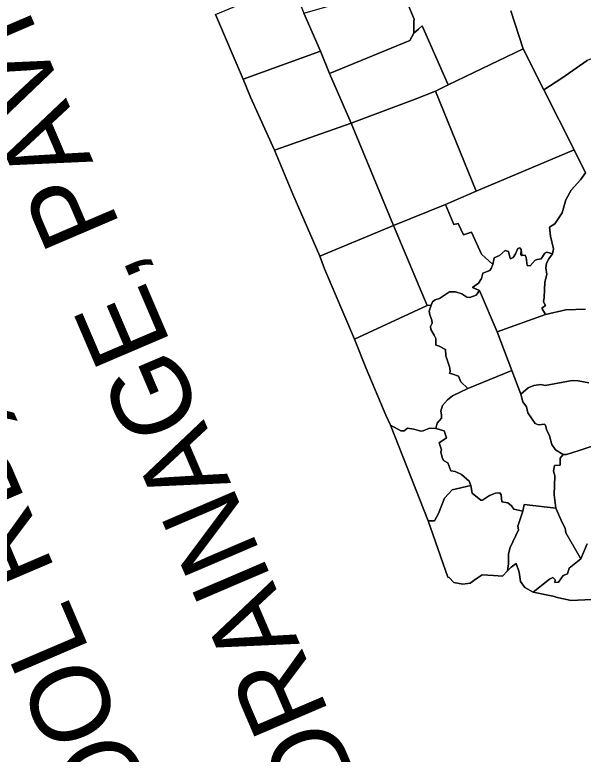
# Model space of a CAD drawing. Extents: x 1550250 to 1553210, y 808906 to 812497.
# Drawn here: x 1551099 to 1551255.1, y 810536 to 810739.3 of the extents above; entities that cross this region are included whole.
import ezdxf

# ---------------------------------------------------------------- set-up
doc = ezdxf.new("R2010")
doc.units = 0
doc.layers.add('P_RDY_Dimension_Text', color=7, linetype='Continuous')
doc.layers.add('Sheet_Data_Field_CELL', color=7, linetype='Continuous')

msp = doc.modelspace()

# ---------------------------------------------------------------- linework, layer by layer
at = {"layer": 'P_RDY_Dimension_Text'}
for points in [[(1551161.74, 810721.58), (1551154.06, 810739.31), (1551175.06, 810748.13), (1551178.36, 810739.68), (1551182.94, 810729.24), (1551161.74, 810721.58)], [(1551182.94, 810729.24), (1551178.36, 810739.68), (1551204.79, 810747.3), (1551208.64, 810738.1), (1551208.56, 810737.4), (1551208.6, 810734.25), (1551207.45, 810732.17), (1551185.41, 810723.16), (1551182.94, 810729.24)], [(1551235.21, 810740.38), (1551238.66, 810729.86), (1551218.05, 810720.05), (1551210.87, 810736.27), (1551209.84, 810735.33), (1551208.6, 810734.25), (1551208.56, 810737.4), (1551208.64, 810738.1), (1551204.79, 810747.3)], [(1551154.06, 810739.31), (1551161.74, 810721.58), (1551163.67, 810716.63), (1551170.28, 810702.09), (1551175.3, 810689.91), (1551182.8, 810672.93), (1551184.07, 810669.38), (1551192.26, 810650.09), (1551195.53, 810642.04), (1551200.89, 810629.19), (1551202.16, 810626.41), (1551212.55, 810600.12), (1551217.97, 810584.69), (1551218.26, 810584.6), (1551219.58, 810583.23), (1551222.04, 810582.69), (1551224.09, 810583), (1551225.71, 810584.23), (1551227.38, 810585.3), (1551230.5, 810585.13), (1551232.95, 810584.94), (1551234.31, 810586.44), (1551235.32, 810587.41), (1551236.67, 810588.39), (1551237.5, 810586.03), (1551237.89, 810583.45), (1551239.04, 810581.78), (1551241.36, 810580.53), (1551247.25, 810579.32), (1551247.63, 810579.17), (1551251.81, 810578.26), (1551257.36, 810578.52)], [(1551265.99, 810739.56), (1551265.11, 810736.8), (1551264.2, 810735.13), (1551263.81, 810733.42), (1551262.28, 810732.86), (1551260.72, 810731.45), (1551260.27, 810730.58), (1551260.7, 810729.58), (1551260.71, 810728.9), (1551259.95, 810728.29), (1551256.16, 810726.73), (1551249.22, 810721.82), (1551244.26, 810718.6), (1551238.66, 810729.86), (1551235.21, 810740.38)], [(1551208.6, 810734.25), (1551209.84, 810735.33), (1551210.87, 810736.27), (1551218.05, 810720.05), (1551214.56, 810718.23), (1551208.96, 810716.05), (1551191.37, 810709.47), (1551185.41, 810723.16), (1551207.45, 810732.17), (1551208.6, 810734.25)], [(1551161.74, 810721.58), (1551182.94, 810729.24), (1551185.41, 810723.16), (1551191.37, 810709.47), (1551170.28, 810702.09), (1551163.67, 810716.63), (1551161.74, 810721.58)], [(1551218.05, 810720.05), (1551238.66, 810729.86), (1551244.26, 810718.6), (1551252.6, 810702.1), (1551225.75, 810690.81), (1551214.56, 810718.23), (1551218.05, 810720.05)], [(1551252.6, 810702.1), (1551244.26, 810718.6), (1551249.22, 810721.82), (1551256.16, 810726.73)], [(1551191.37, 810709.47), (1551208.96, 810716.05), (1551214.56, 810718.23), (1551225.75, 810690.81), (1551217.26, 810687.07), (1551203.02, 810681.34), (1551191.37, 810709.47)], [(1551175.3, 810689.91), (1551170.28, 810702.09), (1551191.37, 810709.47), (1551203.02, 810681.34), (1551182.8, 810672.93), (1551175.3, 810689.91)], [(1551219.56, 810681.58), (1551217.26, 810687.07), (1551225.75, 810690.81), (1551252.6, 810702.1), (1551255.79, 810695.77), (1551254.36, 810693.86), (1551251.81, 810691.07), (1551250.34, 810688.38), (1551249.35, 810684.8), (1551247.29, 810681.78), (1551245.84, 810680.89), (1551246.17, 810678.41), (1551247, 810674.96), (1551246.69, 810673.59), (1551245.14, 810674.04), (1551244.55, 810673.71), (1551243.53, 810672.16), (1551242.48, 810671.97), (1551241.93, 810671.83), (1551240.57, 810670.27), (1551239.72, 810670.3), (1551239.46, 810672.55), (1551239.13, 810673.14), (1551238.3, 810673.1), (1551238, 810673.28), (1551238.03, 810674.74), (1551237.74, 810675.18), (1551237.19, 810675.03), (1551236.48, 810673.56), (1551235.91, 810672.56), (1551235.16, 810672.19), (1551234.95, 810672.65), (1551234.63, 810674.19), (1551233.71, 810674.46), (1551232.12, 810673.11), (1551230.69, 810672.47), (1551230.25, 810670.64), (1551227.13, 810673.43), (1551224.42, 810679.5), (1551222.25, 810678.76), (1551220.74, 810681.89), (1551219.56, 810681.58)], [(1551255.79, 810695.77), (1551252.6, 810702.1)], [(1551243.79, 810658.61), (1551244.79, 810659.31), (1551244.17, 810660.34), (1551244.37, 810661.51), (1551244.57, 810665.76), (1551245.1, 810667.87), (1551244.87, 810669.69), (1551245.02, 810671.01), (1551245.63, 810672.2), (1551246.69, 810673.59), (1551247, 810674.96), (1551246.17, 810678.41), (1551245.84, 810680.89), (1551247.29, 810681.78), (1551249.35, 810684.8), (1551250.34, 810688.38), (1551251.81, 810691.07), (1551254.36, 810693.86), (1551255.79, 810695.77)], [(1551212.26, 810659.31), (1551203.02, 810681.34), (1551217.26, 810687.07), (1551219.56, 810681.58), (1551220.74, 810681.89), (1551222.25, 810678.76), (1551224.42, 810679.5), (1551227.13, 810673.43), (1551230.25, 810670.64), (1551229.87, 810669.52), (1551229.42, 810668.97), (1551227.51, 810668.21), (1551227.14, 810666.74), (1551226.37, 810665.51), (1551224.74, 810664.31), (1551225.71, 810663.87), (1551226.67, 810663.44), (1551225.74, 810662.16), (1551223.96, 810661.52), (1551223.16, 810661.66), (1551221.81, 810662.59), (1551220.07, 810663.08), (1551218.38, 810663.06), (1551217.59, 810662.51), (1551215.65, 810661.23), (1551214.46, 810660.92), (1551213.75, 810660.39), (1551213.33, 810659.42), (1551212.26, 810659.31)], [(1551182.8, 810672.93), (1551203.02, 810681.34), (1551212.26, 810659.31), (1551192.26, 810650.09), (1551184.07, 810669.38), (1551182.8, 810672.93)], [(1551224.74, 810664.31), (1551226.37, 810665.51), (1551227.14, 810666.74), (1551227.51, 810668.21), (1551229.42, 810668.97), (1551229.87, 810669.52), (1551230.25, 810670.64), (1551230.69, 810672.47), (1551232.12, 810673.11), (1551233.71, 810674.46), (1551234.63, 810674.19), (1551234.95, 810672.65), (1551235.16, 810672.19), (1551235.91, 810672.56), (1551236.48, 810673.56), (1551237.19, 810675.03), (1551237.74, 810675.18), (1551238.03, 810674.74), (1551238, 810673.28), (1551238.3, 810673.1), (1551239.13, 810673.14), (1551239.46, 810672.55), (1551239.72, 810670.3), (1551240.57, 810670.27), (1551241.93, 810671.83), (1551242.48, 810671.97), (1551243.53, 810672.16), (1551244.55, 810673.71), (1551245.14, 810674.04), (1551246.69, 810673.59), (1551245.63, 810672.2), (1551245.02, 810671.01), (1551244.87, 810669.69), (1551245.1, 810667.87), (1551244.57, 810665.76), (1551244.37, 810661.51), (1551244.17, 810660.34), (1551244.79, 810659.31), (1551243.79, 810658.61), (1551244.76, 810656.9), (1551231.5, 810652.09), (1551226.67, 810663.44), (1551225.71, 810663.87), (1551224.74, 810664.31)], [(1551213.25, 810652.76), (1551213.19, 810653.61), (1551213.63, 810654.5), (1551213.49, 810655.33), (1551212.95, 810656.73), (1551212.82, 810657.82), (1551213.33, 810659.42), (1551213.75, 810660.39), (1551214.46, 810660.92), (1551215.65, 810661.23), (1551217.59, 810662.51), (1551218.38, 810663.06), (1551220.07, 810663.08), (1551221.81, 810662.59), (1551223.16, 810661.66), (1551223.96, 810661.52), (1551225.74, 810662.16), (1551226.67, 810663.44), (1551231.5, 810652.09), (1551235.49, 810641.46), (1551223.42, 810636.51), (1551221.46, 810638.4), (1551220.89, 810639.88), (1551219.28, 810640.49), (1551218.36, 810640.76), (1551218.53, 810641.06), (1551218.5, 810642.09), (1551218.4, 810642.49), (1551218.24, 810643.06), (1551217.41, 810645.51), (1551217.29, 810647.2), (1551215.32, 810648.23), (1551214.65, 810648.48), (1551214.6, 810649.33), (1551214.59, 810650.28), (1551214.18, 810651.2), (1551213.25, 810652.76)], [(1551212.26, 810659.31), (1551213.33, 810659.42), (1551212.82, 810657.82), (1551212.95, 810656.73), (1551213.49, 810655.33), (1551213.63, 810654.5), (1551213.19, 810653.61), (1551213.25, 810652.76), (1551214.18, 810651.2), (1551214.59, 810650.28), (1551214.6, 810649.33), (1551214.65, 810648.48), (1551215.32, 810648.23), (1551217.29, 810647.2), (1551217.41, 810645.51), (1551218.24, 810643.06), (1551218.4, 810642.49), (1551218.5, 810642.09), (1551218.53, 810641.06), (1551218.36, 810640.76), (1551219.28, 810640.49), (1551220.89, 810639.88), (1551221.46, 810638.4), (1551223.42, 810636.51), (1551219.2, 810634.52), (1551217.81, 810633.37), (1551216.43, 810631.88), (1551216.01, 810630.3), (1551216.2, 810629.31), (1551216.2, 810628.36), (1551214.96, 810626.99), (1551214.67, 810625.53), (1551212.85, 810625.65), (1551211.19, 810624.86), (1551210.54, 810624.77), (1551208.58, 810625.37), (1551206.82, 810625.58), (1551205.89, 810624.9), (1551205.03, 810624.93), (1551202.16, 810626.41), (1551200.89, 810629.19), (1551195.53, 810642.04), (1551192.26, 810650.09), (1551212.26, 810659.31)], [(1551255.77, 810658.37), (1551250.35, 810658.13), (1551244.76, 810656.9), (1551243.79, 810658.61)], [(1551244.76, 810656.9), (1551250.35, 810658.13), (1551255.77, 810658.37)], [(1551256.67, 810638.06), (1551253.71, 810638.63), (1551252.09, 810638.71), (1551244.65, 810637.39), (1551243.5, 810637.59), (1551241.54, 810637.33), (1551240, 810636.74), (1551238.02, 810635), (1551235.49, 810641.46), (1551231.5, 810652.09), (1551244.76, 810656.9)], [(1551214.67, 810625.53), (1551214.96, 810626.99), (1551216.2, 810628.36), (1551216.2, 810629.31), (1551216.01, 810630.3), (1551216.43, 810631.88), (1551217.81, 810633.37), (1551219.2, 810634.52), (1551223.42, 810636.51), (1551235.49, 810641.46), (1551238.02, 810635), (1551238.51, 810632.9), (1551239.58, 810631.47), (1551239.94, 810629.84), (1551241.95, 810626.86), (1551242.81, 810626.49), (1551244.46, 810626.68), (1551244.78, 810626.42), (1551245.01, 810625.28), (1551245.84, 810623.53), (1551246.5, 810621.12), (1551247.5, 810619.67), (1551249.64, 810618.37), (1551248.82, 810617.37), (1551248.83, 810615.48), (1551247.27, 810615.31), (1551246.91, 810613.83), (1551247.29, 810612.47), (1551247.13, 810607.26), (1551247.56, 810603.58), (1551238.92, 810604.66), (1551238.5, 810602.82), (1551236.05, 810603.35), (1551235.44, 810604.31), (1551234.38, 810605.05), (1551232.76, 810605.39), (1551232.56, 810607.32), (1551232.17, 810607.82), (1551230.99, 810607.75), (1551229.37, 810607.14), (1551227.44, 810605.83), (1551227.02, 810605.8), (1551224.61, 810607.74), (1551224.26, 810609.89), (1551223.77, 810611.06), (1551221.64, 810612.9), (1551219.96, 810613.74), (1551218.72, 810613.92), (1551217.94, 810616.13), (1551216.74, 810616.76), (1551216.36, 810617.52), (1551216.02, 810619.07), (1551216.21, 810619.64), (1551215.57, 810621.63), (1551217.52, 810622.93), (1551216.89, 810624.92), (1551214.67, 810625.53)], [(1551238.02, 810635), (1551240, 810636.74), (1551241.54, 810637.33), (1551243.5, 810637.59), (1551244.65, 810637.39), (1551252.09, 810638.71), (1551253.71, 810638.63), (1551256.67, 810638.06)], [(1551257.88, 810620.79), (1551254, 810619.47), (1551250.5, 810618.34), (1551249.64, 810618.37), (1551247.5, 810619.67), (1551246.5, 810621.12), (1551245.84, 810623.53), (1551245.01, 810625.28), (1551244.78, 810626.42), (1551244.46, 810626.68), (1551242.81, 810626.49), (1551241.95, 810626.86), (1551239.94, 810629.84), (1551239.58, 810631.47), (1551238.51, 810632.9), (1551238.02, 810635)], [(1551202.16, 810626.41), (1551205.03, 810624.93), (1551205.89, 810624.9), (1551206.82, 810625.58), (1551208.58, 810625.37), (1551210.54, 810624.77), (1551211.19, 810624.86), (1551212.85, 810625.65), (1551214.67, 810625.53), (1551216.89, 810624.92), (1551217.52, 810622.93), (1551215.57, 810621.63), (1551216.21, 810619.64), (1551216.02, 810619.07), (1551216.36, 810617.52), (1551216.74, 810616.76), (1551217.94, 810616.13), (1551218.72, 810613.92), (1551219.96, 810613.74), (1551221.64, 810612.9), (1551223.77, 810611.06), (1551224.26, 810609.89), (1551219.14, 810608.67), (1551218.1, 810607.52), (1551216.97, 810606.35), (1551215.39, 810602.19), (1551214.25, 810600.15), (1551212.55, 810600.12), (1551202.16, 810626.41)], [(1551256.17, 810593.81), (1551254.44, 810589.7), (1551250.3, 810596.84), (1551250.2, 810598.1), (1551249.34, 810599.68), (1551247.56, 810603.58), (1551247.13, 810607.26), (1551247.29, 810612.47), (1551246.91, 810613.83), (1551247.27, 810615.31), (1551248.83, 810615.48), (1551248.82, 810617.37), (1551249.64, 810618.37), (1551250.5, 810618.34), (1551254, 810619.47), (1551257.88, 810620.79)], [(1551212.55, 810600.12), (1551214.25, 810600.15), (1551215.39, 810602.19), (1551216.97, 810606.35), (1551218.1, 810607.52), (1551219.14, 810608.67), (1551224.26, 810609.89), (1551224.61, 810607.74), (1551227.02, 810605.8), (1551227.44, 810605.83), (1551229.37, 810607.14), (1551230.99, 810607.75), (1551232.17, 810607.82), (1551232.56, 810607.32), (1551232.76, 810605.39), (1551234.38, 810605.05), (1551235.44, 810604.31), (1551236.05, 810603.35), (1551238.5, 810602.82), (1551237.19, 810598.66), (1551237.38, 810597.67), (1551235.08, 810592.8), (1551234.62, 810591.11), (1551234.63, 810588.35), (1551234.31, 810586.44), (1551232.95, 810584.94), (1551230.5, 810585.13), (1551227.38, 810585.3), (1551225.71, 810584.23), (1551224.09, 810583), (1551222.04, 810582.69), (1551219.58, 810583.23), (1551218.26, 810584.6), (1551217.97, 810584.69), (1551212.55, 810600.12)], [(1551234.31, 810586.44), (1551234.63, 810588.35), (1551234.62, 810591.11), (1551235.08, 810592.8), (1551237.38, 810597.67), (1551237.19, 810598.66), (1551238.5, 810602.82), (1551238.92, 810604.66), (1551247.56, 810603.58), (1551249.34, 810599.68), (1551250.2, 810598.1), (1551250.3, 810596.84), (1551254.44, 810589.7), (1551251.24, 810587.17), (1551250.76, 810585.57), (1551249.62, 810585.08), (1551248.35, 810583.26), (1551247.33, 810583.23), (1551247.39, 810583.94), (1551246.79, 810584.55), (1551245.89, 810584.13), (1551241.36, 810580.53), (1551239.04, 810581.78), (1551237.89, 810583.45), (1551237.5, 810586.03), (1551236.67, 810588.39), (1551235.32, 810587.41), (1551234.31, 810586.44)], [(1551254.44, 810589.7), (1551256.17, 810593.81)], [(1551257.36, 810578.52), (1551251.81, 810578.26), (1551247.63, 810579.17), (1551247.25, 810579.32), (1551241.36, 810580.53), (1551245.89, 810584.13), (1551246.79, 810584.55), (1551247.39, 810583.94), (1551247.33, 810583.23), (1551248.35, 810583.26), (1551249.62, 810585.08), (1551250.76, 810585.57), (1551251.24, 810587.17), (1551254.44, 810589.7)]]:
    msp.add_lwpolyline(points, dxfattribs=at)
msp.add_lwpolyline([(1551230.69, 810672.47), (1551232.12, 810673.11), (1551233.71, 810674.46), (1551234.63, 810674.19), (1551234.95, 810672.65), (1551235.16, 810672.19), (1551235.91, 810672.56), (1551236.48, 810673.56), (1551237.19, 810675.03), (1551237.74, 810675.18), (1551238.03, 810674.74), (1551238.3, 810673.1), (1551239.13, 810673.14), (1551239.46, 810672.55), (1551239.72, 810670.3), (1551240.57, 810670.27), (1551241.93, 810671.83), (1551242.48, 810671.97), (1551243.53, 810672.16), (1551244.55, 810673.71), (1551245.14, 810674.04), (1551246.69, 810673.59), (1551245.63, 810672.2), (1551245.02, 810671.01), (1551244.87, 810669.69), (1551245.1, 810667.87), (1551244.57, 810665.76), (1551244.37, 810661.51), (1551244.17, 810660.34), (1551244.79, 810659.31), (1551243.79, 810658.61), (1551244.76, 810656.9), (1551231.5, 810652.09), (1551226.67, 810663.44), (1551224.74, 810664.31), (1551226.37, 810665.51), (1551227.14, 810666.74), (1551227.51, 810668.21), (1551229.42, 810668.97), (1551229.87, 810669.52), (1551230.25, 810670.64)], close=True, dxfattribs=at)

# ---------------------------------------------------------------- texts
at = {"layer": 'Sheet_Data_Field_CELL'}
for s, p in [('GRADING, DRAINAGE, PAVING, AND STRUCTURE', (1551252.97, 810389.57)), ('REPLACEMENT OF BRIDGE NO. 76 ON SR 1436', (1551204.03, 810279.9)), ('(PINEBROOK SCHOOL RD)', (1551235.72, 810293.46))]:
    msp.add_text(s, height=21.5627, rotation=113.1736, dxfattribs=at).set_placement(p)

doc.saveas('drawing.dxf')
